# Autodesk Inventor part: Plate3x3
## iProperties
Created: 2006-02
Part Number: Plate3x3
Material: Stainless Steel
Document SubType Name: Modeling
Designer: 40664
Mass: 200889 g
Surface Area: 50370 cm^2
Volume: 24862.5 cm^3
Density: 8.08 g/cm^3
CSToolsMass: 201.0
CSToolsVolume: 24862500.0
CSToolsArea: 50370.0
Author: 40664
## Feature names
1. Extrusion2
